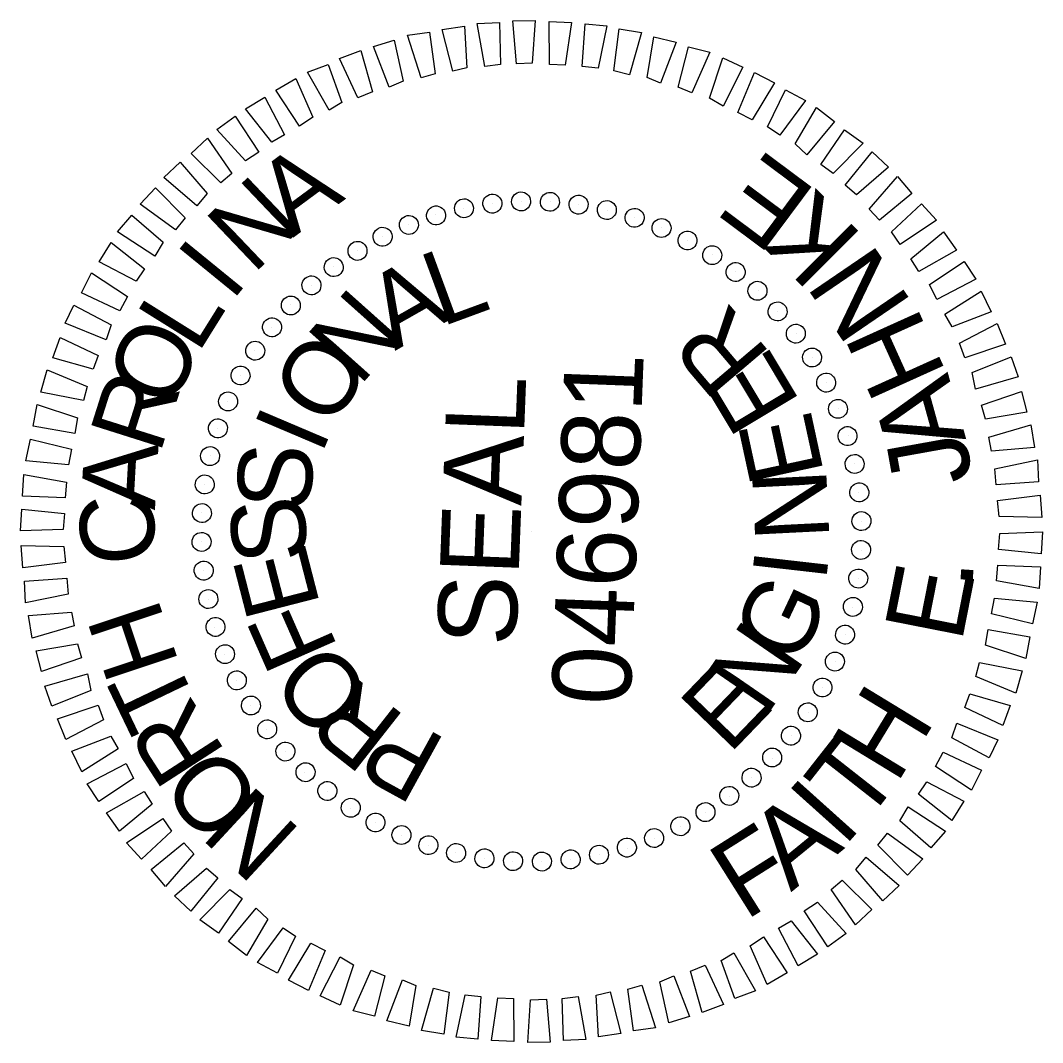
# Model space of a CAD drawing. Extents: x 2097098 to 2098257, y 686470 to 688528.
# Drawn here: x 2097293.4 to 2097371, y 688450.7 to 688528.3 of the extents above; entities that cross this region are included whole.
import ezdxf

# ---------------------------------------------------------------- set-up
doc = ezdxf.new("R2010")
doc.units = 0
doc.layers.add('Sheet PE Seal Cell', color=7, linetype='Continuous')

msp = doc.modelspace()

# ---------------------------------------------------------------- linework, layer by layer
at = {"layer": 'Sheet PE Seal Cell'}
for p, q in [((2097329.245, 688514.375), (2097329.245, 688514.375)), ((2097331.405, 688514.592), (2097331.405, 688514.592)), ((2097333.605, 688514.558), (2097333.605, 688514.558)), ((2097335.798, 688514.324), (2097335.798, 688514.324)), ((2097324.91, 688513.541), (2097324.91, 688513.541)), ((2097327.031, 688514.06), (2097327.031, 688514.06)), ((2097337.933, 688513.892), (2097337.933, 688513.892)), ((2097322.881, 688512.818), (2097322.881, 688512.818)), ((2097340.014, 688513.362), (2097340.014, 688513.362)), ((2097320.894, 688511.893), (2097320.894, 688511.893)), ((2097342.086, 688512.582), (2097342.086, 688512.582)), ((2097344.05, 688511.606), (2097344.05, 688511.606)), ((2097318.951, 688510.817), (2097318.951, 688510.817)), ((2097345.96, 688510.532), (2097345.96, 688510.532)), ((2097317.155, 688509.635), (2097317.155, 688509.635)), ((2097347.711, 688509.214), (2097347.711, 688509.214)), ((2097315.448, 688508.199), (2097315.448, 688508.199)), ((2097349.408, 688507.798), (2097349.408, 688507.798)), ((2097313.89, 688506.708), (2097313.89, 688506.708)), ((2097350.899, 688506.239), (2097350.899, 688506.239)), ((2097312.474, 688505.011), (2097312.474, 688505.011)), ((2097352.335, 688504.533), (2097352.335, 688504.533)), ((2097311.156, 688503.26), (2097311.156, 688503.26)), ((2097353.517, 688502.736), (2097353.517, 688502.736)), ((2097310.082, 688501.35), (2097310.082, 688501.35)), ((2097354.593, 688500.794), (2097354.593, 688500.794)), ((2097309.106, 688499.386), (2097309.106, 688499.386)), ((2097355.518, 688498.807), (2097355.518, 688498.807)), ((2097308.326, 688497.314), (2097308.326, 688497.314)), ((2097356.24, 688496.778), (2097356.24, 688496.778)), ((2097307.796, 688495.233), (2097307.796, 688495.233)), ((2097356.76, 688494.656), (2097356.76, 688494.656)), ((2097307.364, 688493.098), (2097307.364, 688493.098)), ((2097357.075, 688492.442), (2097357.075, 688492.442)), ((2097307.129, 688490.905), (2097307.129, 688490.905)), ((2097357.292, 688490.282), (2097357.292, 688490.282)), ((2097332.194, 688489.494), (2097332.194, 688489.494)), ((2097307.095, 688488.705), (2097307.095, 688488.705)), ((2097357.258, 688488.082), (2097357.258, 688488.082)), ((2097307.312, 688486.545), (2097307.312, 688486.545)), ((2097357.024, 688485.89), (2097357.024, 688485.89)), ((2097307.628, 688484.331), (2097307.628, 688484.331)), ((2097356.592, 688483.755), (2097356.592, 688483.755)), ((2097308.147, 688482.21), (2097308.147, 688482.21)), ((2097356.062, 688481.673), (2097356.062, 688481.673)), ((2097308.87, 688480.181), (2097308.87, 688480.181)), ((2097355.282, 688479.602), (2097355.282, 688479.602)), ((2097309.794, 688478.194), (2097309.794, 688478.194)), ((2097354.306, 688477.638), (2097354.306, 688477.638)), ((2097310.871, 688476.251), (2097310.871, 688476.251)), ((2097353.232, 688475.727), (2097353.232, 688475.727)), ((2097312.053, 688474.455), (2097312.053, 688474.455)), ((2097351.914, 688473.977), (2097351.914, 688473.977)), ((2097313.488, 688472.748), (2097313.488, 688472.748)), ((2097350.497, 688472.28), (2097350.497, 688472.28)), ((2097314.98, 688471.19), (2097314.98, 688471.19)), ((2097348.939, 688470.788), (2097348.939, 688470.788)), ((2097316.677, 688469.774), (2097316.677, 688469.774)), ((2097347.233, 688469.353), (2097347.233, 688469.353)), ((2097318.427, 688468.456), (2097318.427, 688468.456)), ((2097345.436, 688468.171), (2097345.436, 688468.171)), ((2097320.338, 688467.382), (2097320.338, 688467.382)), ((2097343.494, 688467.094), (2097343.494, 688467.094)), ((2097322.302, 688466.406), (2097322.302, 688466.406)), ((2097341.507, 688466.17), (2097341.507, 688466.17)), ((2097324.373, 688465.626), (2097324.373, 688465.626)), ((2097339.477, 688465.447), (2097339.477, 688465.447)), ((2097326.454, 688465.096), (2097326.454, 688465.096)), ((2097328.589, 688464.664), (2097328.589, 688464.664)), ((2097335.142, 688464.612), (2097335.142, 688464.612)), ((2097337.356, 688464.928), (2097337.356, 688464.928)), ((2097330.782, 688464.429), (2097330.782, 688464.429)), ((2097332.982, 688464.395), (2097332.982, 688464.395))]:
    msp.add_line(p, q, dxfattribs=at)
for points in [[(2097328.644, 688524.806), (2097328.069, 688528.08), (2097329.774, 688528.165), (2097329.851, 688524.96)], [(2097331.054, 688525.014), (2097330.779, 688528.276), (2097332.482, 688528.311), (2097332.257, 688525.067)], [(2097333.554, 688524.968), (2097333.529, 688528.221), (2097335.228, 688528.156), (2097334.753, 688524.922)], [(2097323.808, 688523.94), (2097322.781, 688527.182), (2097324.441, 688527.419), (2097324.87, 688524.25)], [(2097326.229, 688524.448), (2097325.4, 688527.632), (2097327.111, 688527.867), (2097327.29, 688524.708)], [(2097336.05, 688524.822), (2097336.275, 688528.066), (2097337.92, 688527.903), (2097337.246, 688524.676)], [(2097338.439, 688524.48), (2097338.861, 688527.666), (2097340.553, 688527.401), (2097339.629, 688524.184)], [(2097321.379, 688523.233), (2097320.197, 688526.331), (2097321.767, 688526.821), (2097322.447, 688523.692)], [(2097340.972, 688523.983), (2097341.49, 688527.065), (2097343.176, 688526.65), (2097342.006, 688523.543)], [(2097318.996, 688522.424), (2097317.61, 688525.429), (2097319.234, 688526.017), (2097320.114, 688522.881)], [(2097343.345, 688523.241), (2097344.114, 688526.314), (2097345.749, 688525.901), (2097344.379, 688522.801)], [(2097345.715, 688522.4), (2097346.733, 688525.463), (2097348.257, 688524.754), (2097346.743, 688521.81)], [(2097316.809, 688521.507), (2097315.168, 688524.372), (2097316.742, 688524.962), (2097317.782, 688522.07)], [(2097347.875, 688521.316), (2097349.143, 688524.37), (2097350.663, 688523.561), (2097348.955, 688520.774)], [(2097314.561, 688520.292), (2097312.764, 688523.013), (2097314.299, 688523.905), (2097315.587, 688520.953)], [(2097350.135, 688520.229), (2097351.493, 688523.029), (2097353.013, 688522.22), (2097351.061, 688519.593)], [(2097312.463, 688519.072), (2097310.458, 688521.6), (2097311.943, 688522.494), (2097313.435, 688519.635)], [(2097352.237, 688518.947), (2097353.843, 688521.688), (2097355.204, 688520.635), (2097353.106, 688518.113)], [(2097310.457, 688517.647), (2097308.296, 688520.032), (2097309.686, 688521.03), (2097311.483, 688518.309)], [(2097354.178, 688517.372), (2097355.98, 688520.005), (2097357.393, 688519), (2097355.103, 688516.686)], [(2097308.591, 688515.968), (2097306.325, 688518.206), (2097307.57, 688519.359), (2097309.419, 688516.687)], [(2097356.019, 688515.8), (2097358.068, 688518.323), (2097359.324, 688517.174), (2097356.892, 688515.066)], [(2097306.773, 688514.236), (2097304.254, 688516.384), (2097305.499, 688517.537), (2097307.559, 688515.157)], [(2097357.851, 688513.978), (2097359.997, 688516.448), (2097361.098, 688515.155), (2097358.62, 688513.148)], [(2097305.152, 688512.397), (2097302.474, 688514.351), (2097303.623, 688515.608), (2097305.887, 688513.319)], [(2097359.536, 688512.263), (2097361.819, 688514.377), (2097362.972, 688513.132), (2097360.199, 688511.286)], [(2097303.574, 688510.406), (2097300.743, 688512.266), (2097301.842, 688513.525), (2097304.216, 688511.482)], [(2097361.009, 688510.205), (2097363.489, 688512.261), (2097364.487, 688510.872), (2097361.622, 688509.23)], [(2097302.15, 688508.509), (2097299.354, 688509.967), (2097300.261, 688511.434), (2097302.786, 688509.435)], [(2097362.435, 688508.249), (2097365.054, 688510), (2097365.953, 688508.664), (2097362.992, 688507.126)], [(2097300.913, 688506.255), (2097298.013, 688507.617), (2097298.772, 688509.139), (2097301.505, 688507.333)], [(2097363.599, 688506.002), (2097366.368, 688507.747), (2097367.108, 688506.168), (2097364.163, 688505.03)], [(2097299.878, 688504.043), (2097296.774, 688505.313), (2097297.427, 688506.689), (2097300.271, 688505.179)], [(2097364.716, 688503.808), (2097367.575, 688505.299), (2097368.215, 688503.724), (2097365.124, 688502.691)], [(2097298.892, 688501.829), (2097295.823, 688502.697), (2097296.382, 688504.227), (2097299.282, 688502.865)], [(2097365.681, 688501.569), (2097368.629, 688502.757), (2097369.171, 688501.235), (2097365.933, 688500.309)], [(2097298.15, 688499.456), (2097294.922, 688500.08), (2097295.387, 688501.763), (2097298.441, 688500.495)], [(2097366.387, 688499.09), (2097369.428, 688500.125), (2097369.819, 688498.558), (2097366.696, 688498.028)], [(2097297.503, 688496.929), (2097294.323, 688497.501), (2097294.636, 688499.14), (2097297.699, 688498.122)], [(2097366.944, 688496.667), (2097370.132, 688497.596), (2097370.417, 688495.884), (2097367.154, 688495.608)], [(2097297.011, 688494.546), (2097293.772, 688494.87), (2097294.135, 688496.507), (2097297.257, 688495.737)], [(2097367.402, 688494.248), (2097370.63, 688494.925), (2097370.717, 688493.27), (2097367.506, 688493.043)], [(2097296.766, 688492.053), (2097293.518, 688492.178), (2097293.631, 688493.825), (2097296.862, 688493.251)], [(2097367.61, 688491.838), (2097370.828, 688492.265), (2097370.963, 688490.559), (2097367.713, 688490.633)], [(2097296.624, 688489.657), (2097293.367, 688489.532), (2097293.48, 688491.179), (2097296.72, 688490.854)], [(2097367.764, 688489.33), (2097371.021, 688489.456), (2097370.908, 688487.809), (2097367.668, 688488.133)], [(2097296.778, 688487.149), (2097293.559, 688486.722), (2097293.424, 688488.429), (2097296.674, 688488.354)], [(2097367.622, 688486.934), (2097370.869, 688486.81), (2097370.756, 688485.163), (2097367.526, 688485.737)], [(2097296.986, 688484.74), (2097293.757, 688484.063), (2097293.671, 688485.717), (2097296.882, 688485.944)], [(2097367.376, 688484.442), (2097370.616, 688484.117), (2097370.253, 688482.48), (2097367.13, 688483.25)], [(2097297.443, 688482.32), (2097294.255, 688481.392), (2097293.971, 688483.104), (2097297.234, 688483.379)], [(2097366.884, 688482.059), (2097370.065, 688481.487), (2097369.752, 688479.847), (2097366.688, 688480.865)], [(2097298.001, 688479.897), (2097294.959, 688478.863), (2097294.569, 688480.429), (2097297.691, 688480.96)], [(2097366.237, 688479.532), (2097369.465, 688478.908), (2097369.001, 688477.224), (2097365.947, 688478.492)], [(2097298.706, 688477.418), (2097295.759, 688476.23), (2097295.217, 688477.752), (2097298.454, 688478.679)], [(2097365.495, 688477.158), (2097368.564, 688476.29), (2097368.005, 688474.761), (2097365.105, 688476.123)], [(2097299.671, 688475.18), (2097296.812, 688473.688), (2097296.172, 688475.264), (2097299.264, 688476.296)], [(2097364.51, 688474.945), (2097367.613, 688473.675), (2097366.96, 688472.299), (2097364.116, 688473.809)], [(2097300.788, 688472.985), (2097298.019, 688471.24), (2097297.279, 688472.82), (2097300.225, 688473.957)], [(2097363.474, 688472.733), (2097366.374, 688471.371), (2097365.615, 688469.848), (2097362.883, 688471.655)], [(2097301.953, 688470.739), (2097299.334, 688468.988), (2097298.434, 688470.323), (2097301.395, 688471.861)], [(2097362.237, 688470.478), (2097365.033, 688469.02), (2097364.126, 688467.554), (2097361.601, 688469.552)], [(2097303.379, 688468.783), (2097300.898, 688466.726), (2097299.901, 688468.116), (2097302.766, 688469.757)], [(2097360.813, 688468.582), (2097363.644, 688466.722), (2097362.545, 688465.463), (2097360.172, 688467.505)], [(2097304.851, 688466.725), (2097302.568, 688464.611), (2097301.415, 688465.856), (2097304.188, 688467.701)], [(2097359.236, 688466.591), (2097361.913, 688464.637), (2097360.764, 688463.38), (2097358.5, 688465.668)], [(2097306.537, 688465.009), (2097304.39, 688462.539), (2097303.289, 688463.833), (2097305.768, 688465.839)], [(2097357.614, 688464.751), (2097360.134, 688462.603), (2097358.889, 688461.45), (2097356.828, 688463.831)], [(2097308.368, 688463.188), (2097306.32, 688460.664), (2097305.063, 688461.813), (2097307.496, 688463.921)], [(2097355.796, 688463.02), (2097358.062, 688460.781), (2097356.817, 688459.628), (2097354.968, 688462.301)], [(2097310.209, 688461.616), (2097308.407, 688458.983), (2097306.994, 688459.988), (2097309.285, 688462.302)], [(2097312.15, 688460.04), (2097310.544, 688457.3), (2097309.183, 688458.353), (2097311.282, 688460.874)], [(2097353.931, 688461.34), (2097356.091, 688458.956), (2097354.702, 688457.958), (2097352.905, 688460.679)], [(2097351.925, 688459.916), (2097353.929, 688457.387), (2097352.444, 688456.493), (2097350.952, 688459.353)], [(2097314.253, 688458.759), (2097312.894, 688455.959), (2097311.374, 688456.768), (2097313.326, 688459.395)], [(2097349.826, 688458.695), (2097351.623, 688455.975), (2097350.088, 688455.083), (2097348.8, 688458.034)], [(2097316.513, 688457.671), (2097315.245, 688454.618), (2097313.725, 688455.427), (2097315.433, 688458.213)], [(2097347.578, 688457.481), (2097349.22, 688454.616), (2097347.646, 688454.026), (2097346.606, 688456.918)], [(2097318.673, 688456.588), (2097317.655, 688453.525), (2097316.131, 688454.233), (2097317.645, 688457.178)], [(2097321.042, 688455.746), (2097320.274, 688452.674), (2097318.638, 688453.086), (2097320.008, 688456.186)], [(2097345.391, 688456.564), (2097346.777, 688453.558), (2097345.154, 688452.97), (2097344.273, 688456.106)], [(2097323.416, 688455.005), (2097322.897, 688451.922), (2097321.212, 688452.337), (2097322.382, 688455.445)], [(2097343.009, 688455.755), (2097344.191, 688452.657), (2097342.621, 688452.167), (2097341.94, 688455.295)], [(2097325.948, 688454.507), (2097325.526, 688451.321), (2097323.835, 688451.586), (2097324.759, 688454.803)], [(2097338.159, 688454.539), (2097338.987, 688451.355), (2097337.277, 688451.121), (2097337.098, 688454.28)], [(2097340.58, 688455.047), (2097341.606, 688451.805), (2097339.946, 688451.569), (2097339.517, 688454.738)], [(2097328.337, 688454.166), (2097328.112, 688450.922), (2097326.468, 688451.085), (2097327.142, 688454.312)], [(2097330.833, 688454.02), (2097330.859, 688450.766), (2097329.16, 688450.832), (2097329.634, 688454.066)], [(2097333.333, 688453.974), (2097333.608, 688450.711), (2097331.906, 688450.676), (2097332.13, 688453.92)], [(2097335.743, 688454.182), (2097336.318, 688450.907), (2097334.613, 688450.823), (2097334.536, 688454.028)]]:
    msp.add_lwpolyline(points, close=True, dxfattribs=at)
for centre, major_axis in [((2097329.223, 688514.397), (-0.085, 0.715)), ((2097331.404, 688514.561), (-0.023, 0.72)), ((2097333.592, 688514.535), (0.04, 0.719)), ((2097335.769, 688514.318), (0.103, 0.713)), ((2097324.943, 688513.503), (-0.208, 0.689)), ((2097327.063, 688514.043), (-0.147, 0.705)), ((2097337.919, 688513.911), (0.164, 0.701)), ((2097322.878, 688512.78), (-0.267, 0.668)), ((2097340.026, 688513.32), (0.225, 0.684)), ((2097320.884, 688511.879), (-0.325, 0.643)), ((2097342.072, 688512.546), (0.284, 0.662)), ((2097344.044, 688511.598), (0.34, 0.635)), ((2097318.976, 688510.808), (-0.379, 0.612)), ((2097345.925, 688510.481), (0.394, 0.602)), ((2097317.169, 688509.575), (-0.431, 0.576)), ((2097347.702, 688509.204), (0.445, 0.566)), ((2097315.476, 688508.189), (-0.48, 0.537)), ((2097349.361, 688507.777), (0.493, 0.525)), ((2097313.91, 688506.661), (-0.525, 0.493)), ((2097350.889, 688506.212), (0.537, 0.48)), ((2097312.483, 688505.002), (-0.566, 0.445)), ((2097352.275, 688504.519), (0.576, 0.431)), ((2097311.207, 688503.225), (-0.602, 0.394)), ((2097353.508, 688502.711), (0.612, 0.379)), ((2097310.09, 688501.344), (-0.635, 0.34)), ((2097354.579, 688500.803), (0.643, 0.325)), ((2097309.141, 688499.372), (-0.662, 0.284)), ((2097355.48, 688498.809), (0.668, 0.267)), ((2097308.368, 688497.326), (-0.684, 0.225)), ((2097356.203, 688496.744), (0.689, 0.208)), ((2097307.776, 688495.219), (-0.701, 0.164)), ((2097356.743, 688494.624), (0.705, 0.147)), ((2097307.37, 688493.069), (-0.713, 0.103)), ((2097357.097, 688492.465), (0.715, 0.085)), ((2097307.153, 688490.892), (-0.719, 0.04)), ((2097357.261, 688490.283), (0.72, 0.023)), ((2097307.126, 688488.704), (-0.72, -0.023)), ((2097357.235, 688488.095), (0.719, -0.04)), ((2097307.29, 688486.523), (-0.715, -0.085)), ((2097357.018, 688485.918), (0.713, -0.103)), ((2097307.644, 688484.363), (-0.705, -0.147)), ((2097356.611, 688483.768), (0.701, -0.164)), ((2097308.185, 688482.243), (-0.689, -0.208)), ((2097356.019, 688481.662), (0.684, -0.225)), ((2097308.908, 688480.178), (-0.668, -0.267)), ((2097355.246, 688479.615), (0.662, -0.284)), ((2097309.808, 688478.184), (-0.643, -0.325)), ((2097354.298, 688477.644), (0.635, -0.34)), ((2097310.879, 688476.276), (-0.612, -0.379)), ((2097353.181, 688475.762), (0.602, -0.394)), ((2097312.112, 688474.469), (-0.576, -0.431)), ((2097351.904, 688473.985), (0.566, -0.445)), ((2097313.498, 688472.776), (-0.537, -0.48)), ((2097350.477, 688472.326), (0.525, -0.493)), ((2097315.026, 688471.21), (-0.493, -0.525)), ((2097348.912, 688470.798), (0.48, -0.537)), ((2097316.685, 688469.783), (-0.445, -0.566)), ((2097347.219, 688469.412), (0.431, -0.576)), ((2097318.462, 688468.507), (-0.394, -0.602)), ((2097345.411, 688468.179), (0.379, -0.612)), ((2097320.344, 688467.39), (-0.34, -0.635)), ((2097343.503, 688467.108), (0.325, -0.643)), ((2097322.315, 688466.441), (-0.284, -0.662)), ((2097341.509, 688466.208), (0.267, -0.668)), ((2097324.362, 688465.668), (-0.225, -0.684)), ((2097339.444, 688465.485), (0.208, -0.689)), ((2097326.468, 688465.076), (-0.164, -0.701)), ((2097328.618, 688464.67), (-0.103, -0.713)), ((2097335.165, 688464.59), (0.085, -0.715)), ((2097337.324, 688464.944), (0.147, -0.705)), ((2097330.795, 688464.453), (-0.04, -0.719)), ((2097332.983, 688464.426), (0.023, -0.72))]:
    msp.add_ellipse(centre, major_axis=major_axis, ratio=0.999708, dxfattribs=at)

# ---------------------------------------------------------------- texts
for s, height, rotation, p in [('A', 5.639, 36.42085, (2097314.085, 688511.804)), ('E', 5.998, 143.29672, (2097353.99, 688515.28)), ('N', 5.639, 43.62261, (2097311.025, 688508.969)), ('K', 5.998, 135.0128, (2097357.478, 688511.87)), ('I', 5.638, 50.82384, (2097309.393, 688506.88)), ('L', 5.639, 20.20455, (2097325.334, 688505.018)), ('N', 5.998, 124.28697, (2097361.2, 688506.774)), ('A', 5.639, 29.56397, (2097321.811, 688503.202)), ('N', 5.639, 48.28031, (2097319.104, 688500.453)), ('L', 5.638, 58.02457, (2097306.84, 688502.925)), ('R', 5.639, 130.28511, (2097350.471, 688502.903)), ('H', 5.998, 114.30299, (2097363.757, 688501.483)), ('O', 5.638, 65.22486, (2097304.823, 688498.599)), ('O', 5.638, 57.63718, (2097316.977, 688497.183)), ('E', 5.638, 120.92779, (2097352.683, 688499.266)), ('046981', 5.9982, 87.8037, (2097339.699, 688476.225)), ('R', 5.638, 72.4248, (2097303.945, 688495.281)), ('SEAL', 5.9982, 87.8037, (2097331.008, 688480.734)), ('A', 5.998, 105.46268, (2097365.225, 688496.49)), ('I', 5.638, 66.9933, (2097316.201, 688495.211)), ('E', 5.638, 102.21546, (2097354.429, 688493.895)), ('J', 5.998, 100.20486, (2097365.727, 688493.434)), ('A', 5.638, 86.82402, (2097303.584, 688491.091)), ('S', 5.638, 85.7041, (2097315.337, 688490.941)), ('N', 5.638, 92.86009, (2097354.839, 688488.926)), ('C', 5.638, 94.02357, (2097303.732, 688487.133)), ('S', 5.638, 95.05931, (2097315.249, 688487.342)), ('E', 5.638, 104.41477, (2097316.166, 688483.854)), ('I', 5.638, 83.5049, (2097354.56, 688485.584)), ('E', 5.998, 78.86139, (2097364.861, 688480.959)), ('.', 5.998, 85.97073, (2097365.666, 688485.067)), ('G', 5.638, 64.79394, (2097352.411, 688479.111)), ('H', 5.638, 108.42318, (2097305.44, 688479.462)), ('F', 5.638, 113.77073, (2097317.542, 688480.599)), ('N', 5.638, 55.43766, (2097350.017, 688475.4)), ('O', 5.639, 132.48494, (2097320.363, 688477.188)), ('E', 5.638, 46.08059, (2097347.204, 688472.506)), ('T', 5.638, 115.62347, (2097306.964, 688476.151)), ('R', 5.639, 141.84335, (2097322.745, 688475.345)), ('H', 5.998, 58.67705, (2097359.91, 688470.211)), ('R', 5.639, 122.82421, (2097309.032, 688472.669)), ('P', 5.639, 151.20259, (2097325.881, 688473.624)), ('T', 5.998, 51.87681, (2097357.431, 688467.065)), ('O', 5.639, 130.02544, (2097311.997, 688469.103)), ('N', 5.639, 137.2272, (2097314.807, 688466.693)), ('I', 5.998, 48.07486, (2097355.889, 688465.441)), ('A', 5.998, 39.23455, (2097351.911, 688462.085)), ('F', 5.998, 32.21794, (2097348.415, 688459.882))]:
    msp.add_text(s, height=height, rotation=rotation, dxfattribs=at).set_placement(p)

doc.saveas('drawing.dxf')
